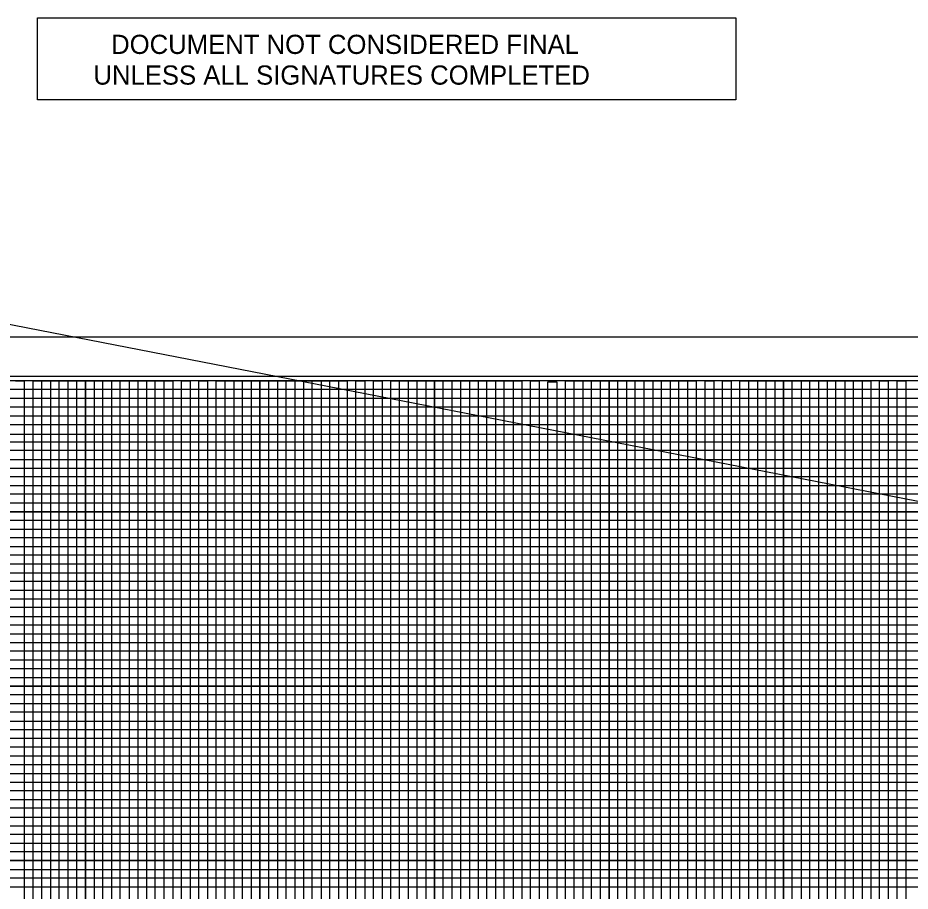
# Model space of a CAD drawing. Extents: x 1632447 to 1634147, y 883210 to 885181.
# Drawn here: x 1633075 to 1633586, y 884680 to 885181 of the extents above; entities that cross this region are included whole.
import ezdxf

# ---------------------------------------------------------------- set-up
doc = ezdxf.new("R2010")
doc.units = 0
for name, color, linetype in [('Scratch_Level_8', 7, 'Continuous'), ('Sheet Cutting Line CELL', 7, 'Continuous'), ('Sheet DOT Grid CELL', 7, 'Continuous'), ('Sheet Plot Border Inside CELL', 7, 'Continuous'), ('Sheet Plot Border Outside CELL', 7, 'Continuous'), ('Sheet Profile CELL', 7, 'Continuous'), ('Sheet Profile Grid Major CELL', 7, 'Continuous'), ('Sheet Profile Grid Middle CELL', 7, 'Continuous'), ('Sheet Profile Grid Minor CELL', 7, 'Continuous'), ('Sheet Sticker Exception Certification CELL', 7, 'Continuous'), ('Stewart Plot Border Xerox6279 and LJ5000', 7, 'Continuous')]:
    doc.layers.add(name, color=color, linetype=linetype)

msp = doc.modelspace()

# ---------------------------------------------------------------- linework, layer by layer
at = {"layer": 'Scratch_Level_8'}
msp.add_lwpolyline([(1632663.86, 883947.61), (1632663.86, 885084.12), (1634063.86, 884811.56), (1634013.86, 884541.53), (1634013.86, 883947.61)], close=True, dxfattribs=at)
at = {"layer": 'Sheet Cutting Line CELL'}
msp.add_line((1634130.86, 884997.61), (1632446.86, 884997.61), dxfattribs=at)
at = {"layer": 'Sheet DOT Grid CELL'}
for p, q in [((1633113.86, 884972.61), (1633113.86, 883947.61)), ((1633163.86, 884972.61), (1633163.86, 883947.61)), ((1633213.86, 884972.61), (1633213.86, 883947.61)), ((1633263.86, 884972.61), (1633263.86, 883947.61)), ((1633313.86, 884972.61), (1633313.86, 883947.61)), ((1633363.86, 884972.61), (1633363.86, 883947.61)), ((1633413.86, 884972.61), (1633413.86, 883947.61)), ((1633463.86, 884972.61), (1633463.86, 883947.61)), ((1633513.86, 884972.61), (1633513.86, 883947.61)), ((1633563.86, 884972.61), (1633563.86, 883947.61)), ((1632613.86, 884947.61), (1633913.81, 884947.61)), ((1632613.86, 884897.61), (1633913.81, 884897.61)), ((1632613.86, 884847.61), (1633913.81, 884847.61)), ((1632613.86, 884797.61), (1633913.81, 884797.61)), ((1632613.86, 884747.61), (1634113.86, 884747.61)), ((1632613.86, 884697.61), (1634113.86, 884697.61))]:
    msp.add_line(p, q, dxfattribs=at)
at = {"layer": 'Sheet Plot Border Inside CELL'}
msp.add_lwpolyline([(1634126.36, 884975.16), (1632459.86, 884975.16), (1632459.86, 883920.06), (1634126.36, 883920.06)], close=True, dxfattribs=at)
at = {"layer": 'Sheet Plot Border Outside CELL'}
msp.add_lwpolyline([(1634130.86, 884997.61), (1632446.86, 884997.61), (1632446.86, 883897.61), (1634130.86, 883897.61)], close=True, dxfattribs=at)
at = {"layer": 'Sheet Profile CELL'}
msp.add_lwpolyline([(1634113.86, 884972.61), (1632613.86, 884972.61), (1632613.86, 883922.61), (1634113.86, 883922.61)], close=True, dxfattribs=at)
at = {"layer": 'Sheet Profile Grid Major CELL'}
for points in [[(1633113.86, 883947.61), (1633113.86, 884972.61), (1633163.86, 884972.61), (1633163.86, 883947.61)], [(1633213.86, 883947.61), (1633213.86, 884972.61), (1633263.86, 884972.61), (1633263.86, 883947.61)], [(1633313.86, 883947.61), (1633313.86, 884972.61), (1633363.86, 884972.61), (1633363.86, 883947.61)], [(1633413.86, 883947.61), (1633413.86, 884972.61), (1633463.86, 884972.61), (1633463.86, 883947.61)], [(1633513.86, 883947.61), (1633513.86, 884972.61), (1633563.86, 884972.61), (1633563.86, 883947.61)], [(1633913.81, 884897.61), (1632613.96, 884897.61), (1632613.96, 884947.56), (1633913.81, 884947.56)], [(1633913.81, 884797.61), (1632613.86, 884797.61), (1632613.86, 884847.61), (1633913.81, 884847.61)], [(1634113.86, 884697.61), (1632613.86, 884697.61), (1632613.86, 884747.61), (1634113.86, 884747.61)]]:
    msp.add_lwpolyline(points, dxfattribs=at)
at = {"layer": 'Sheet Profile Grid Middle CELL'}
for points in [[(1633088.86, 883947.61), (1633088.86, 884972.61), (1633138.86, 884972.61), (1633138.86, 883947.61)], [(1633188.86, 883947.61), (1633188.86, 884972.61), (1633238.86, 884972.61), (1633238.86, 883947.61)], [(1633288.86, 883947.61), (1633288.86, 884972.61), (1633338.86, 884972.61), (1633338.86, 883947.61)], [(1633388.86, 883947.61), (1633388.86, 884972.61), (1633438.86, 884972.61), (1633438.86, 883947.61)], [(1633488.86, 883947.61), (1633488.86, 884972.61), (1633538.86, 884972.61), (1633538.86, 883947.61)], [(1632613.86, 884922.61), (1633913.81, 884922.61)], [(1633913.81, 884872.61), (1632613.86, 884872.61), (1632613.86, 884822.56), (1633913.81, 884822.56)], [(1633913.83, 884772.61), (1632613.86, 884772.61), (1632613.86, 884722.61), (1634113.86, 884722.61)]]:
    msp.add_lwpolyline(points, dxfattribs=at)
at = {"layer": 'Sheet Profile Grid Minor CELL'}
for p, q in [((1633913.86, 884792.61), (1632663.86, 884792.61)), ((1632663.86, 884787.61), (1633913.83, 884787.61)), ((1634063.86, 884767.61), (1632663.86, 884767.61))]:
    msp.add_line(p, q, dxfattribs=at)
for points in [[(1633073.86, 884972.61), (1633078.86, 884972.61), (1633078.86, 883947.61), (1633083.86, 883947.61), (1633083.86, 884972.61), (1633093.86, 884972.61), (1633093.86, 883947.61), (1633098.86, 883947.61), (1633098.86, 884972.61), (1633103.86, 884972.61), (1633103.86, 883947.61), (1633108.86, 883947.61), (1633108.86, 884972.61), (1633118.86, 884972.61), (1633118.86, 883947.61), (1633123.86, 883947.61), (1633123.86, 884972.61), (1633128.86, 884972.61), (1633128.86, 883947.61), (1633133.86, 883947.61), (1633133.86, 884972.61), (1633143.86, 884972.61), (1633143.86, 883947.61)], [(1633148.86, 884972.61), (1633148.86, 883947.61), (1633153.86, 883947.61), (1633153.86, 884972.61), (1633158.86, 884972.61), (1633158.86, 883947.61), (1633168.86, 883947.61), (1633168.86, 884972.61), (1633173.86, 884972.61), (1633173.86, 883947.61), (1633178.86, 883947.61), (1633178.86, 884972.61), (1633183.86, 884972.61), (1633183.86, 883947.61)], [(1633193.86, 883947.61), (1633193.86, 884972.61), (1633198.86, 884972.61), (1633198.86, 883947.61)], [(1633203.86, 883947.61), (1633203.86, 884972.61), (1633208.86, 884972.61), (1633208.86, 883947.61)], [(1633218.86, 883947.61), (1633218.86, 884972.61), (1633223.86, 884972.61), (1633223.86, 883947.61)], [(1633228.86, 883947.61), (1633228.86, 884972.61), (1633233.86, 884972.61), (1633233.86, 883947.61)], [(1633243.86, 883947.61), (1633243.86, 884972.61), (1633248.86, 884972.61), (1633248.86, 883947.61)], [(1633253.86, 883947.61), (1633253.86, 884972.61), (1633258.86, 884972.61), (1633258.86, 883947.61)], [(1633268.86, 883947.61), (1633268.86, 884972.61), (1633273.86, 884972.61), (1633273.86, 883947.61)], [(1633278.86, 883947.61), (1633278.86, 884972.61), (1633283.86, 884972.61), (1633283.86, 883947.61)], [(1633293.86, 883947.61), (1633293.86, 884972.61), (1633298.86, 884972.61), (1633298.86, 883947.61)], [(1633303.86, 883947.61), (1633303.86, 884972.61), (1633308.86, 884972.61), (1633308.86, 883947.61)], [(1633318.86, 883947.61), (1633318.86, 884972.61), (1633323.86, 884972.61), (1633323.86, 883947.61)], [(1633328.86, 883947.61), (1633328.86, 884972.61), (1633333.86, 884972.61), (1633333.86, 883947.61)], [(1633343.86, 883947.61), (1633343.86, 884972.61), (1633348.86, 884972.61), (1633348.86, 883947.61)], [(1633353.86, 883947.61), (1633353.86, 884972.61), (1633358.86, 884972.61), (1633358.86, 883947.61)], [(1633368.86, 883947.61), (1633368.86, 884972.61), (1633373.86, 884972.61), (1633373.86, 883947.61)], [(1633378.86, 883947.61), (1633378.86, 884972.01), (1633383.86, 884972.01), (1633383.86, 883947.61)], [(1633393.86, 883947.61), (1633393.86, 884972.61), (1633398.86, 884972.61), (1633398.86, 883947.61)], [(1633403.86, 883947.61), (1633403.86, 884972.61), (1633408.86, 884972.61), (1633408.86, 883947.61)], [(1633418.86, 883947.61), (1633418.86, 884972.61), (1633423.86, 884972.61), (1633423.86, 883947.61)], [(1633428.86, 883947.61), (1633428.86, 884972.61), (1633433.86, 884972.61), (1633433.86, 883947.61)], [(1633443.86, 883947.61), (1633443.86, 884972.61), (1633448.86, 884972.61), (1633448.86, 883947.61)], [(1633453.86, 883947.61), (1633453.86, 884972.61), (1633458.86, 884972.61), (1633458.86, 883947.61)], [(1633468.86, 883947.61), (1633468.86, 884972.61), (1633473.86, 884972.61), (1633473.86, 883947.61)], [(1633478.86, 883947.61), (1633478.86, 884972.61), (1633483.86, 884972.61), (1633483.86, 883947.61)], [(1633493.86, 883947.61), (1633493.86, 884972.61), (1633498.86, 884972.61), (1633498.86, 883947.61)], [(1633503.86, 883947.61), (1633503.86, 884972.61), (1633508.86, 884972.61), (1633508.86, 883947.61)], [(1633518.86, 883947.61), (1633518.86, 884972.61), (1633523.86, 884972.61), (1633523.86, 883947.61)], [(1633528.86, 883947.61), (1633528.86, 884972.61), (1633533.86, 884972.61), (1633533.86, 883947.61)], [(1633543.86, 883947.61), (1633543.86, 884972.61), (1633548.86, 884972.61), (1633548.86, 883947.61)], [(1633553.86, 883947.61), (1633553.86, 884972.61), (1633558.86, 884972.61), (1633558.86, 883947.61)], [(1633568.86, 883947.61), (1633568.86, 884972.61), (1633573.86, 884972.61), (1633573.86, 883947.61)], [(1633578.86, 883947.61), (1633578.86, 884972.61), (1633583.86, 884972.61), (1633583.86, 883947.61)], [(1633913.81, 884967.61), (1632663.86, 884967.61), (1632663.86, 884962.61), (1633913.81, 884962.61)], [(1633913.81, 884957.61), (1632663.86, 884957.61), (1632663.86, 884952.61), (1633913.81, 884952.61)], [(1633913.81, 884941.86), (1632664.86, 884941.86), (1632664.86, 884937.61), (1633913.81, 884937.61)], [(1633913.81, 884932.61), (1632663.86, 884932.61), (1632663.86, 884927.61), (1633913.81, 884927.61)], [(1633913.81, 884917.61), (1632663.86, 884917.61), (1632663.86, 884912.61), (1633913.81, 884912.61)], [(1633913.81, 884907.61), (1632663.86, 884907.61), (1632663.86, 884902.61), (1633913.81, 884902.61)], [(1633913.81, 884892.61), (1632663.86, 884892.61), (1632663.86, 884887.61), (1633913.81, 884887.61)], [(1633913.81, 884882.61), (1632663.86, 884882.61), (1632663.86, 884877.61), (1633913.81, 884877.61)], [(1633913.81, 884867.61), (1632663.86, 884867.61), (1632663.86, 884862.61), (1633913.81, 884862.61)], [(1633913.81, 884857.61), (1632663.86, 884857.61), (1632663.86, 884852.61), (1633913.81, 884852.61)], [(1633913.81, 884842.61), (1632663.86, 884842.61), (1632663.86, 884837.61), (1633913.81, 884837.61)], [(1633913.81, 884832.61), (1632663.86, 884832.61), (1632663.86, 884832.61), (1632663.86, 884812.61), (1633913.81, 884812.61)], [(1632663.86, 884827.61), (1633913.81, 884827.61)], [(1633913.81, 884817.61), (1632663.86, 884817.61)], [(1633913.81, 884807.61), (1632663.86, 884807.61), (1632663.86, 884802.61), (1633913.81, 884802.61)], [(1633913.83, 884782.61), (1632663.86, 884782.61), (1632663.86, 884777.61), (1633913.83, 884777.61)], [(1634063.86, 884762.61), (1632663.86, 884762.61), (1632663.86, 884757.61), (1634063.86, 884757.61)], [(1634063.86, 884752.61), (1632663.86, 884752.61)], [(1632663.86, 884742.61), (1634063.86, 884742.61)], [(1634063.86, 884737.61), (1632663.86, 884737.61), (1632663.86, 884732.61), (1634063.86, 884732.61)], [(1634063.86, 884727.61), (1632663.86, 884727.61), (1632663.86, 884717.61), (1634063.86, 884717.61)], [(1634063.86, 884712.61), (1632663.86, 884712.61), (1632663.86, 884707.61), (1634063.86, 884707.61)], [(1634063.86, 884702.61), (1632663.86, 884702.61), (1632663.86, 884692.61), (1634063.86, 884692.61)], [(1634063.86, 884687.61), (1632663.86, 884687.61), (1632663.86, 884682.61), (1634063.86, 884682.61)]]:
    msp.add_lwpolyline(points, dxfattribs=at)
at = {"layer": 'Sheet Sticker Exception Certification CELL'}
for p, q in [((1633086.45, 885133.68), (1633086.45, 885180.68)), ((1633086.45, 885180.68), (1633486.52, 885180.68)), ((1633486.52, 885180.66), (1633486.52, 885133.66)), ((1633486.52, 885133.68), (1633086.45, 885133.68))]:
    msp.add_line(p, q, dxfattribs=at)
at = {"layer": 'Stewart Plot Border Xerox6279 and LJ5000'}
msp.add_lwpolyline([(1632446.86, 883897.61), (1634146.86, 883897.61), (1634146.86, 884997.61), (1632446.86, 884997.61)], close=True, dxfattribs=at)

# ---------------------------------------------------------------- texts
at = {"layer": 'Sheet Sticker Exception Certification CELL'}
for s, p in [('DOCUMENT NOT CONSIDERED FINAL', (1633128.59, 885159.99)), ('UNLESS ALL SIGNATURES COMPLETED', (1633118.44, 885142.39))]:
    msp.add_text(s, height=11, rotation=0, dxfattribs=at).set_placement(p)

doc.saveas('drawing.dxf')
